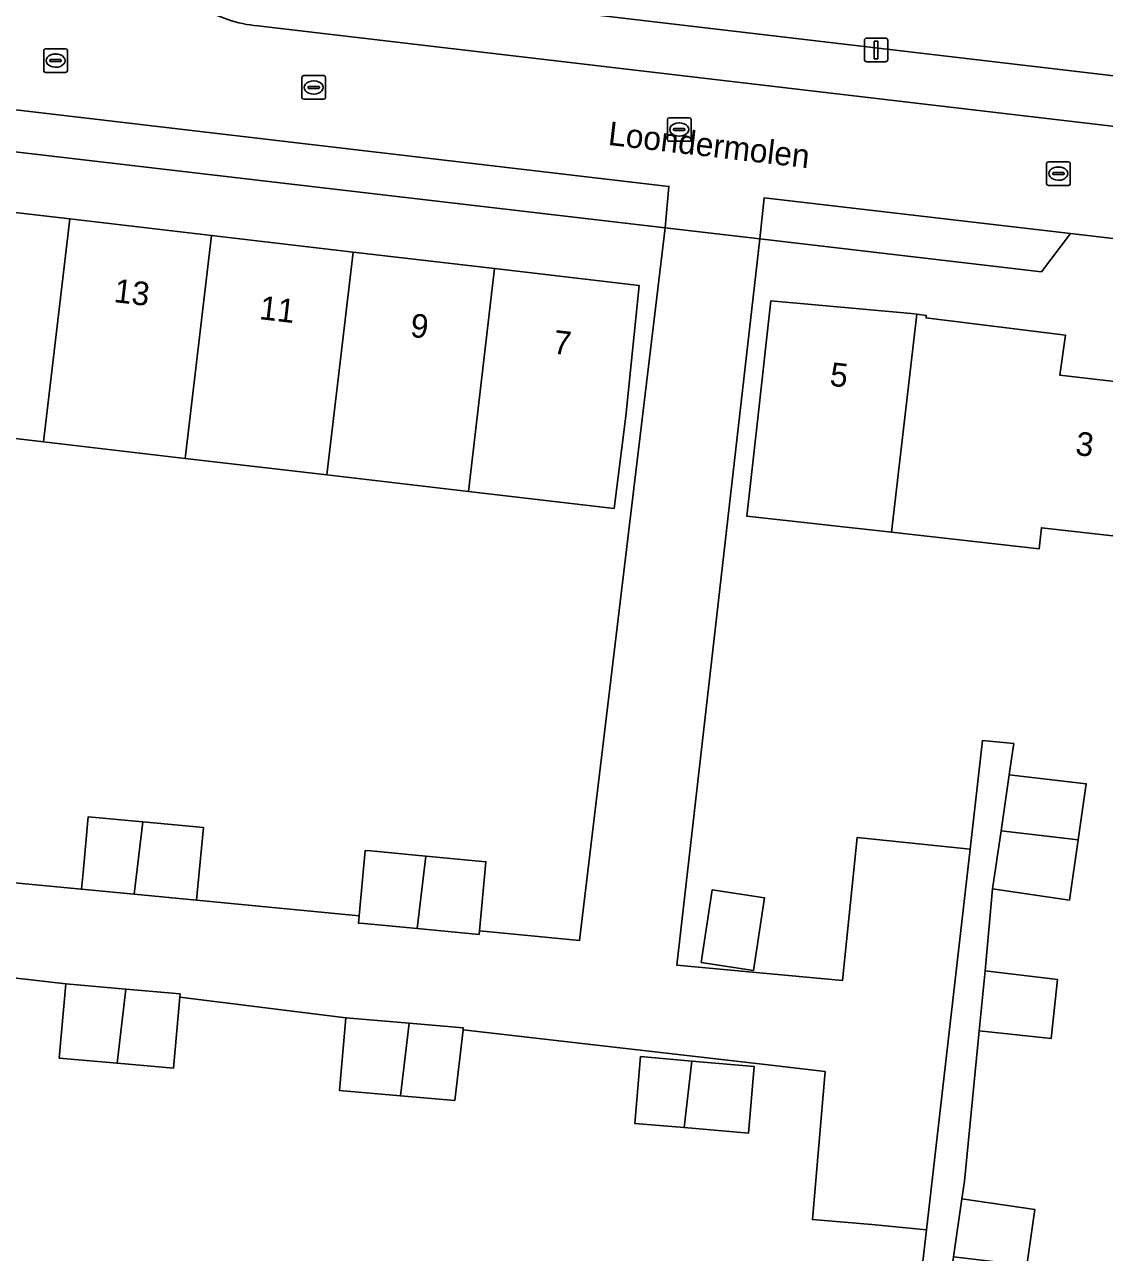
# Model space of a CAD drawing. Extents: x 161241 to 161758, y 384138 to 384885.
# Drawn here: x 161387.9 to 161433.6, y 384527.4 to 384579.4 of the extents above; entities that cross this region are included whole.
import ezdxf

# ---------------------------------------------------------------- set-up
doc = ezdxf.new("R2010")
doc.units = 0
for name, color, linetype in [('IMGEO_Erf', 7, 'Continuous'), ('IMGEO_Kolk', 7, 'Continuous'), ('IMGEO_Lichtmast', 7, 'Continuous'), ('IMGEO_Openbare_ruimte_label', 7, 'Continuous'), ('IMGEO_Pand', 7, 'Continuous'), ('IMGEO_Pand_nummerreeks', 7, 'Continuous'), ('IMGEO_Parkeervlak_open', 7, 'Continuous'), ('IMGEO_Rijbaan_lokaal_open', 7, 'Continuous'), ('IMGEO_Rioolput', 7, 'Continuous'), ('IMGEO_Voetpad_open', 7, 'Continuous')]:
    doc.layers.add(name, color=color, linetype=linetype)

msp = doc.modelspace()

# ---------------------------------------------------------------- linework, layer by layer
at = {"layer": 'IMGEO_Erf'}
for points in [[(161393.526, 384581.977), (161448.824, 384575.465)], [(161414.97, 384570.779), (161379.272, 384574.949), (161378.37, 384576.849), (161360.348, 384578.831)], [(161357.485, 384576.07), (161354.08, 384546.72), (161377.34, 384544.021), (161390.293, 384542.794), (161390.36, 384543.501), (161390.582, 384545.866), (161392.883, 384545.649), (161395.45, 384545.408), (161395.217, 384542.927), (161395.161, 384542.336), (161402.036, 384541.672), (161402.295, 384544.437), (161402.53, 384544.415), (161404.855, 384544.197), (161407.398, 384543.958), (161407.123, 384541.032), (161411.359, 384540.633), (161414.97, 384570.779)], [(161383.809, 384571.858), (161389.798, 384571.158), (161395.787, 384570.457), (161401.776, 384569.757), (161407.766, 384569.056), (161413.877, 384568.341), (161413.316, 384562.809), (161412.813, 384558.909), (161406.662, 384559.627), (161400.673, 384560.327), (161394.684, 384561.027), (161388.693, 384561.726), (161382.705, 384562.426)], [(161450.255, 384568.412), (161432.118, 384570.547), (161430.891, 384568.919), (161418.982, 384570.31), (161415.467, 384539.585), (161422.472, 384538.934), (161423.093, 384544.983), (161427.873, 384544.493), (161428.401, 384549.094), (161429.717, 384548.959), (161429.638, 384548.415), (161429.525, 384547.641), (161432.785, 384547.259), (161432.44, 384544.89), (161432.069, 384542.338), (161428.822, 384542.81), (161428.505, 384539.351), (161431.565, 384538.972), (161431.305, 384536.488), (161428.258, 384536.808), (161427.632, 384530.446), (161427.522, 384529.694), (161430.611, 384529.244), (161430.266, 384526.874)], [(161439.684, 384557.106), (161430.889, 384558.093), (161430.788, 384557.198), (161424.542, 384557.899), (161418.425, 384558.585), (161418.89, 384562.729), (161419.447, 384567.697), (161425.386, 384567.153), (161425.621, 384567.124), (161426.028, 384567.075), (161426.007, 384566.969), (161431.905, 384566.233), (161431.664, 384564.552), (161440.436, 384563.525)], [(161425.565, 384524.36), (161426.026, 384528.384), (161423.722, 384528.608), (161421.212, 384528.819), (161421.738, 384535.09), (161419.21, 384535.381), (161406.432, 384536.854), (161406.08, 384533.855), (161403.791, 384534.055), (161401.206, 384534.28), (161401.474, 384537.359), (161394.449, 384538.235), (161394.187, 384535.23), (161391.807, 384535.437), (161389.352, 384535.651), (161389.625, 384538.791), (161382.609, 384539.597), (161382.266, 384536.529), (161379.995, 384536.783), (161380.337, 384539.851), (161353.642, 384542.948), (161349.844, 384510.209)]]:
    msp.add_lwpolyline(points, dxfattribs=at)
for points in [[(161416.499, 384539.691), (161416.97, 384542.773), (161419.177, 384542.435), (161418.706, 384539.354)], [(161413.938, 384535.714), (161416.109, 384535.524), (161418.746, 384535.294), (161418.5, 384532.471), (161415.778, 384532.709), (161413.692, 384532.891)]]:
    msp.add_lwpolyline(points, close=True, dxfattribs=at)
at = {"layer": 'IMGEO_Kolk'}
for p, q in [((161399.615, 384576.294), (161399.615, 384577.146)), ((161399.69, 384577.22), (161400.542, 384577.22)), ((161400.103, 384577), (161400.128, 384577)), ((161400.616, 384577.146), (161400.616, 384576.294)), ((161399.874, 384576.714), (161399.874, 384576.726)), ((161400.312, 384576.677), (161399.914, 384576.677)), ((161399.917, 384576.763), (161400.315, 384576.763)), ((161400.126, 384576.44), (161400.101, 384576.44)), ((161400.358, 384576.726), (161400.358, 384576.714)), ((161400.542, 384576.22), (161399.69, 384576.22)), ((161415.07, 384574.514), (161415.07, 384575.366)), ((161415.145, 384575.44), (161415.997, 384575.44)), ((161416.071, 384575.366), (161416.071, 384574.514)), ((161415.329, 384574.934), (161415.329, 384574.946)), ((161415.767, 384574.897), (161415.369, 384574.897)), ((161415.372, 384574.983), (161415.77, 384574.983)), ((161415.558, 384575.22), (161415.583, 384575.22)), ((161415.813, 384574.946), (161415.813, 384574.934)), ((161415.997, 384574.44), (161415.145, 384574.44)), ((161415.581, 384574.66), (161415.556, 384574.66)), ((161431.106, 384572.648), (161431.106, 384573.5)), ((161431.181, 384573.574), (161432.033, 384573.574)), ((161431.594, 384573.354), (161431.619, 384573.354)), ((161432.107, 384573.5), (161432.107, 384572.648)), ((161431.365, 384573.068), (161431.365, 384573.08)), ((161431.803, 384573.031), (161431.405, 384573.031)), ((161431.408, 384573.117), (161431.806, 384573.117)), ((161431.617, 384572.794), (161431.592, 384572.794)), ((161431.849, 384573.08), (161431.849, 384573.068)), ((161432.033, 384572.574), (161431.181, 384572.574))]:
    msp.add_line(p, q, dxfattribs=at)
for points in [[(161399.615, 384576.294), (161399.615, 384577.146)], [(161399.69, 384577.22), (161400.542, 384577.22)], [(161400.616, 384577.146), (161400.616, 384576.294)], [(161400.542, 384576.22), (161399.69, 384576.22)], [(161415.07, 384574.514), (161415.07, 384575.366)], [(161415.145, 384575.44), (161415.997, 384575.44)], [(161416.071, 384575.366), (161416.071, 384574.514)], [(161415.997, 384574.44), (161415.145, 384574.44)], [(161431.106, 384572.648), (161431.106, 384573.5)], [(161431.181, 384573.574), (161432.033, 384573.574)], [(161432.107, 384573.5), (161432.107, 384572.648)], [(161432.033, 384572.574), (161431.181, 384572.574)]]:
    msp.add_lwpolyline(points, dxfattribs=at)
for centre, radius, start, end in [((161399.692, 384577.144), 0.0765, 91.552, 178.448), ((161399.692, 384577.144), 0.0765, 91.552, 178.448), ((161400.54, 384577.144), 0.0765, 1.552, 88.448), ((161400.54, 384577.144), 0.0765, 1.552, 88.448), ((161399.914, 384576.723), 0.0403, 85.8775, 175.7526), ((161399.911, 384576.713), 0.0366, 178.938, 274.7102), ((161400.315, 384576.72), 0.043, 264.8664, 352.4533), ((161400.319, 384576.725), 0.0386, 1.7309, 96.639), ((161399.692, 384576.296), 0.0765, 181.552, 268.448), ((161399.692, 384576.296), 0.0765, 181.552, 268.448), ((161400.54, 384576.296), 0.0765, 271.552, 358.448), ((161400.54, 384576.296), 0.0765, 271.552, 358.448), ((161415.147, 384575.364), 0.0765, 91.552, 178.448), ((161415.147, 384575.364), 0.0765, 91.552, 178.448), ((161415.995, 384575.364), 0.0765, 1.552, 88.448), ((161415.995, 384575.364), 0.0765, 1.552, 88.448), ((161415.369, 384574.943), 0.0403, 85.8775, 175.7526), ((161415.366, 384574.933), 0.0366, 178.938, 274.7102), ((161415.77, 384574.94), 0.043, 264.8664, 352.4533), ((161415.774, 384574.945), 0.0386, 1.7309, 96.639), ((161415.147, 384574.516), 0.0765, 181.552, 268.448), ((161415.147, 384574.516), 0.0765, 181.552, 268.448), ((161415.995, 384574.516), 0.0765, 271.552, 358.448), ((161415.995, 384574.516), 0.0765, 271.552, 358.448), ((161431.183, 384573.498), 0.0765, 91.552, 178.448), ((161431.183, 384573.498), 0.0765, 91.552, 178.448), ((161432.031, 384573.498), 0.0765, 1.552, 88.448), ((161432.031, 384573.498), 0.0765, 1.552, 88.448), ((161431.405, 384573.077), 0.0403, 85.8775, 175.7526), ((161431.402, 384573.067), 0.0366, 178.938, 274.7102), ((161431.806, 384573.074), 0.043, 264.8664, 352.4533), ((161431.81, 384573.079), 0.0386, 1.7309, 96.639), ((161431.183, 384572.65), 0.0765, 181.552, 268.448), ((161431.183, 384572.65), 0.0765, 181.552, 268.448), ((161432.031, 384572.65), 0.0765, 271.552, 358.448), ((161432.031, 384572.65), 0.0765, 271.552, 358.448)]:
    msp.add_arc(centre, radius, start, end, dxfattribs=at)
for centre, major_axis, ratio, start_param, end_param in [((161400.102, 384576.72), (-0.387, 0.002), 0.722429, 4.712389, 7.853982), ((161400.127, 384576.72), (-0.39, 0.002), 0.717154, 1.570796, 4.712389), ((161415.557, 384574.94), (-0.387, 0.002), 0.722429, 4.712389, 7.853982), ((161415.582, 384574.94), (-0.39, 0.002), 0.717154, 1.570796, 4.712389), ((161431.593, 384573.074), (-0.387, 0.002), 0.722429, 4.712389, 7.853982), ((161431.618, 384573.074), (-0.39, 0.002), 0.717154, 1.570796, 4.712389)]:
    msp.add_ellipse(centre, major_axis=major_axis, ratio=ratio, start_param=start_param, end_param=end_param, dxfattribs=at)
at = {"layer": 'IMGEO_Lichtmast'}
for p, q in [((161423.4, 384577.907), (161423.4, 384578.707)), ((161423.4, 384578.707), (161423.4, 384577.907)), ((161423.5, 384578.807), (161424.29, 384578.807)), ((161424.29, 384578.807), (161423.5, 384578.807)), ((161424.39, 384578.707), (161424.39, 384577.907)), ((161424.39, 384577.907), (161424.39, 384578.707)), ((161424.29, 384577.807), (161423.5, 384577.807)), ((161423.5, 384577.807), (161424.29, 384577.807))]:
    msp.add_line(p, q, dxfattribs=at)
msp.add_lwpolyline([(161423.82, 384578.682), (161423.97, 384578.682), (161423.97, 384577.932), (161423.82, 384577.932), (161423.82, 384578.682)], dxfattribs=at)
for centre, start, end in [((161423.5, 384578.707), 90, 180), ((161423.5, 384578.707), 90, 180), ((161424.29, 384578.707), 0, 90), ((161424.29, 384578.707), 360, 90), ((161423.5, 384577.907), 180, 270), ((161423.5, 384577.907), 180, 270), ((161424.29, 384577.907), 270, 0), ((161424.29, 384577.907), 270, 0)]:
    msp.add_arc(centre, 0.1, start, end, dxfattribs=at)
at = {"layer": 'IMGEO_Pand'}
for points in [[(161382.705, 384562.426), (161388.693, 384561.726), (161389.798, 384571.158), (161383.809, 384571.858)], [(161388.693, 384561.726), (161394.684, 384561.027), (161395.787, 384570.457), (161389.798, 384571.158)], [(161401.776, 384569.757), (161395.787, 384570.457), (161394.684, 384561.027), (161400.673, 384560.327)], [(161400.673, 384560.327), (161406.662, 384559.627), (161407.766, 384569.056), (161401.776, 384569.757)], [(161406.662, 384559.627), (161412.813, 384558.909), (161413.316, 384562.809), (161413.877, 384568.341), (161407.766, 384569.056)], [(161425.621, 384567.124), (161425.386, 384567.153), (161419.447, 384567.697), (161418.89, 384562.729), (161418.425, 384558.585), (161424.542, 384557.899)], [(161424.542, 384557.899), (161430.788, 384557.198), (161430.889, 384558.093), (161439.684, 384557.106), (161440.436, 384563.525), (161431.664, 384564.552), (161431.905, 384566.233), (161426.007, 384566.969), (161426.028, 384567.075), (161425.621, 384567.124)], [(161429.525, 384547.641), (161429.18, 384545.273), (161432.44, 384544.89), (161432.785, 384547.259)], [(161392.883, 384545.649), (161390.582, 384545.866), (161390.36, 384543.501), (161390.293, 384542.794), (161392.525, 384542.584)], [(161395.45, 384545.408), (161392.883, 384545.649), (161392.525, 384542.584), (161395.161, 384542.336), (161395.217, 384542.927)], [(161432.44, 384544.89), (161429.18, 384545.273), (161428.822, 384542.81), (161432.069, 384542.338)], [(161404.855, 384544.197), (161402.53, 384544.415), (161402.295, 384544.437), (161402.036, 384541.672), (161402.007, 384541.365), (161402.241, 384541.343), (161404.496, 384541.131)], [(161407.398, 384543.958), (161404.855, 384544.197), (161404.496, 384541.131), (161407.109, 384540.886), (161407.123, 384541.032)], [(161416.499, 384539.691), (161418.706, 384539.354), (161419.177, 384542.435), (161416.97, 384542.773)], [(161428.505, 384539.351), (161428.258, 384536.808), (161431.305, 384536.488), (161431.565, 384538.972)], [(161392.174, 384538.569), (161389.625, 384538.791), (161389.352, 384535.651), (161391.807, 384535.437)], [(161394.449, 384538.235), (161394.461, 384538.369), (161392.174, 384538.569), (161391.807, 384535.437), (161394.187, 384535.23)], [(161404.151, 384537.125), (161401.474, 384537.359), (161401.206, 384534.28), (161403.791, 384534.055)], [(161406.432, 384536.854), (161406.44, 384536.926), (161404.151, 384537.125), (161403.791, 384534.055), (161406.08, 384533.855)], [(161415.778, 384532.709), (161416.109, 384535.524), (161413.938, 384535.714), (161413.692, 384532.891)], [(161416.109, 384535.524), (161415.778, 384532.709), (161418.5, 384532.471), (161418.746, 384535.294)], [(161427.522, 384529.694), (161427.164, 384527.238), (161430.266, 384526.874), (161430.611, 384529.244)]]:
    msp.add_lwpolyline(points, close=True, dxfattribs=at)
at = {"layer": 'IMGEO_Parkeervlak_open'}
for points in [[(161378.37, 384576.849), (161379.272, 384574.949), (161414.97, 384570.779), (161415.137, 384572.53)], [(161418.982, 384570.31), (161430.891, 384568.919), (161432.118, 384570.547), (161419.169, 384572.05)]]:
    msp.add_lwpolyline(points, close=True, dxfattribs=at)
at = {"layer": 'IMGEO_Rijbaan_lokaal_open'}
for points in [[(161358.492, 384579.061), (161360.348, 384578.831), (161378.37, 384576.849), (161415.137, 384572.53), (161414.97, 384570.779), (161418.982, 384570.31), (161419.169, 384572.05), (161432.118, 384570.547), (161450.255, 384568.412), (161450.399, 384568.382), (161450.927, 384573.072), (161397.745, 384579.321)], [(161382.609, 384539.597), (161389.625, 384538.791), (161392.174, 384538.569), (161394.461, 384538.369), (161394.449, 384538.235), (161401.474, 384537.359), (161404.151, 384537.125), (161406.44, 384536.926), (161406.432, 384536.854), (161419.21, 384535.381), (161421.738, 384535.09), (161421.212, 384528.819), (161423.722, 384528.608), (161426.026, 384528.384), (161427.873, 384544.493), (161423.093, 384544.983), (161422.472, 384538.934), (161415.467, 384539.585), (161418.982, 384570.31), (161414.97, 384570.779), (161411.359, 384540.633), (161407.123, 384541.032), (161407.109, 384540.886), (161404.496, 384541.131), (161402.241, 384541.343), (161402.007, 384541.365), (161402.036, 384541.672), (161395.161, 384542.336), (161392.525, 384542.584), (161390.293, 384542.794), (161377.34, 384544.021)]]:
    msp.add_lwpolyline(points, dxfattribs=at)
msp.add_arc((161398.286, 384584.86), 5.565, 237.8125, 264.4264, dxfattribs=at)
at = {"layer": 'IMGEO_Rioolput'}
for p, q in [((161388.697, 384577.429), (161388.697, 384578.281)), ((161388.772, 384578.355), (161389.624, 384578.355)), ((161388.956, 384577.849), (161388.956, 384577.861)), ((161388.999, 384577.898), (161389.397, 384577.898)), ((161389.185, 384578.135), (161389.21, 384578.135)), ((161389.44, 384577.861), (161389.44, 384577.849)), ((161389.698, 384578.281), (161389.698, 384577.429)), ((161389.624, 384577.355), (161388.772, 384577.355)), ((161389.394, 384577.812), (161388.996, 384577.812)), ((161389.208, 384577.575), (161389.183, 384577.575))]:
    msp.add_line(p, q, dxfattribs=at)
for points in [[(161388.697, 384577.429), (161388.697, 384578.281)], [(161388.772, 384578.355), (161389.624, 384578.355)], [(161389.698, 384578.281), (161389.698, 384577.429)], [(161389.624, 384577.355), (161388.772, 384577.355)]]:
    msp.add_lwpolyline(points, dxfattribs=at)
for centre, radius, start, end in [((161388.774, 384578.279), 0.0765, 91.552, 178.448), ((161388.774, 384578.279), 0.0765, 91.552, 178.448), ((161388.996, 384577.858), 0.0403, 85.8775, 175.7526), ((161389.401, 384577.86), 0.0386, 1.7309, 96.639), ((161389.622, 384578.279), 0.0765, 1.552, 88.448), ((161389.622, 384578.279), 0.0765, 1.552, 88.448), ((161388.774, 384577.431), 0.0765, 181.552, 268.448), ((161388.774, 384577.431), 0.0765, 181.552, 268.448), ((161388.993, 384577.848), 0.0366, 178.938, 274.7102), ((161389.397, 384577.855), 0.043, 264.8664, 352.4533), ((161389.622, 384577.431), 0.0765, 271.552, 358.448), ((161389.622, 384577.431), 0.0765, 271.552, 358.448)]:
    msp.add_arc(centre, radius, start, end, dxfattribs=at)
for centre, major_axis, ratio, start_param, end_param in [((161389.184, 384577.855), (-0.387, 0.002), 0.722429, 4.712389, 7.853982), ((161389.209, 384577.855), (-0.39, 0.002), 0.717154, 1.570796, 4.712389)]:
    msp.add_ellipse(centre, major_axis=major_axis, ratio=ratio, start_param=start_param, end_param=end_param, dxfattribs=at)
at = {"layer": 'IMGEO_Voetpad_open'}
for points in [[(161448.824, 384575.465), (161393.526, 384581.977)], [(161397.745, 384579.321), (161450.927, 384573.072), (161451.231, 384576.957)]]:
    msp.add_lwpolyline(points, dxfattribs=at)
msp.add_lwpolyline([(161428.258, 384536.808), (161428.505, 384539.351), (161428.822, 384542.81), (161429.18, 384545.273), (161429.525, 384547.641), (161429.638, 384548.415), (161429.717, 384548.959), (161428.401, 384549.094), (161427.873, 384544.493), (161426.026, 384528.384), (161425.565, 384524.36), (161426.712, 384524.187), (161426.804, 384524.768), (161427.164, 384527.238), (161427.522, 384529.694), (161427.632, 384530.446)], close=True, dxfattribs=at)
msp.add_arc((161398.286, 384584.86), 5.565, 237.8125, 264.4264, dxfattribs=at)

# ---------------------------------------------------------------- texts
at = {"layer": 'IMGEO_Openbare_ruimte_label'}
msp.add_text('Loondermolen', height=1, rotation=353.337, dxfattribs=at).set_placement((161412.533, 384574.292))
at = {"layer": 'IMGEO_Pand_nummerreeks'}
for s, rotation, p in [('13', 353.3276, (161391.633, 384567.641)), ('11', 353.3276, (161397.784, 384566.92)), ('9', 353.3276, (161404.165, 384566.174)), ('7', 353.3276, (161410.203, 384565.468)), ('5', 353.2976, (161421.906, 384564.105)), ('3', 353.3225, (161432.296, 384561.175))]:
    msp.add_text(s, height=1, rotation=rotation, dxfattribs=at).set_placement(p)

doc.saveas('drawing.dxf')
